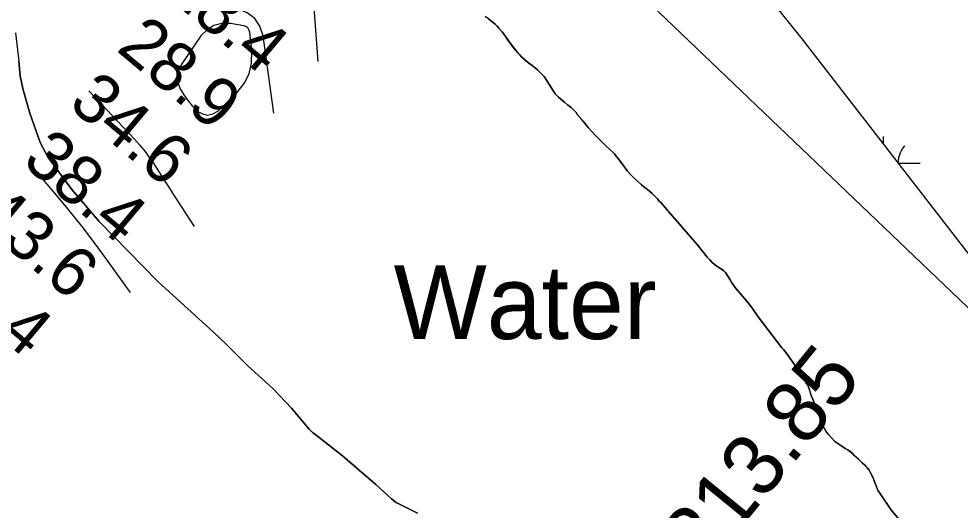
# Model space of a CAD drawing. Extents: x 3172231 to 3210228, y 940198 to 965780.
# Drawn here: x 3194853 to 3196129, y 948241 to 948908 of the extents above; entities that cross this region are included whole.
import ezdxf

# ---------------------------------------------------------------- set-up
doc = ezdxf.new("R2010")
doc.units = 0
for name, color, linetype in [('V-RIVR-IDEN', 7, 'Continuous'), ('V-RIVR-RANG', 7, 'Continuous'), ('V-RIVR-RANG-IDEN', 7, 'Continuous'), ('V-SITE-VEGE', 7, 'Continuous'), ('V-TOPO-BNDY', 7, 'Continuous'), ('V-TOPO-MAJR', 7, 'Continuous'), ('V-TOPO-MINR', 7, 'Continuous'), ('V-TOPO-SHOR', 7, 'Continuous'), ('V-WETL-SWMP', 7, 'Continuous')]:
    doc.layers.add(name, color=color, linetype=linetype)

msp = doc.modelspace()

# ---------------------------------------------------------------- linework, layer by layer
at = {"layer": 'V-SITE-VEGE'}
for p, q in [((3195489.691, 948907.734), (3195496.234, 948902.883)), ((3195496.234, 948902.883), (3195498.919, 948900.468)), ((3195498.919, 948900.468), (3195501.594, 948897.664)), ((3195501.594, 948897.664), (3195503.877, 948894.871)), ((3195503.877, 948894.871), (3195508.463, 948890.062)), ((3195508.463, 948890.062), (3195510.738, 948886.878)), ((3195510.738, 948886.878), (3195513.003, 948883.3)), ((3195513.003, 948883.3), (3195519.446, 948874.141)), ((3195519.446, 948874.141), (3195529.336, 948861.769)), ((3195529.336, 948861.769), (3195532.01, 948858.965)), ((3195532.01, 948858.965), (3195534.296, 948856.17)), ((3194854.602, 948830.054), (3194852.908, 948850.378)), ((3195534.296, 948856.17), (3195538.136, 948852.946)), ((3195538.136, 948852.946), (3195541.585, 948849.735)), ((3195541.585, 948849.735), (3195544.278, 948847.712)), ((3195544.278, 948847.712), (3195548.9, 948844.472)), ((3195548.9, 948844.472), (3195553.514, 948840.839)), ((3195553.514, 948840.839), (3195556.199, 948838.426)), ((3195556.199, 948838.426), (3195565.008, 948829.425)), ((3194858.761, 948811.525), (3194854.602, 948830.054)), ((3195565.008, 948829.425), (3195572.561, 948818.067)), ((3194867.627, 948779.88), (3194858.761, 948811.525)), ((3195572.561, 948818.067), (3195580.112, 948806.143)), ((3195580.112, 948806.143), (3195584.697, 948801.337)), ((3195584.697, 948801.337), (3195590.075, 948796.903)), ((3195590.075, 948796.903), (3195592.76, 948794.49)), ((3195592.76, 948794.49), (3195596.991, 948791.258)), ((3195596.991, 948791.258), (3195601.989, 948787.226)), ((3195601.989, 948787.226), (3195608.485, 948780.414)), ((3194881.783, 948740.151), (3194867.627, 948779.88)), ((3195608.485, 948780.414), (3195610.379, 948777.629)), ((3195610.379, 948777.629), (3195618.004, 948768.833)), ((3195618.004, 948768.833), (3195624.854, 948760.45)), ((3195624.854, 948760.45), (3195634.781, 948749.643)), ((3195634.781, 948749.643), (3195641.288, 948743.225)), ((3195641.288, 948743.225), (3195649.314, 948734.814)), ((3194892.871, 948719.464), (3194881.783, 948740.151)), ((3195649.314, 948734.814), (3195654.301, 948730.388)), ((3195654.301, 948730.388), (3195658.132, 948726.773)), ((3194924.828, 948675.964), (3194892.871, 948719.464)), ((3195658.132, 948726.773), (3195660.424, 948724.371)), ((3195660.424, 948724.371), (3195662.699, 948721.184)), ((3195662.699, 948721.184), (3195664.993, 948718.782)), ((3195664.993, 948718.782), (3195666.896, 948716.388)), ((3195666.896, 948716.388), (3195669.169, 948713.201)), ((3195669.169, 948713.201), (3195671.072, 948710.807)), ((3195671.072, 948710.807), (3195677.906, 948701.638)), ((3195677.906, 948701.638), (3195683.245, 948695.639)), ((3195683.245, 948695.639), (3195686.686, 948692.035)), ((3195686.686, 948692.035), (3195697.032, 948682.393)), ((3195697.032, 948682.393), (3195700.499, 948679.962)), ((3195700.499, 948679.962), (3195705.114, 948676.329)), ((3194961.972, 948632.68), (3194924.828, 948675.964)), ((3195705.114, 948676.329), (3195707.798, 948673.914)), ((3195707.798, 948673.914), (3195711.638, 948670.693)), ((3195711.638, 948670.693), (3195714.313, 948667.889)), ((3195714.313, 948667.889), (3195718.909, 948663.474)), ((3195718.909, 948663.474), (3195720.801, 948660.688)), ((3195720.801, 948660.688), (3195723.867, 948657.874)), ((3195723.867, 948657.874), (3195731.494, 948649.08)), ((3195731.494, 948649.08), (3195732.63, 948647.487)), ((3195732.63, 948647.487), (3195733.777, 948646.285)), ((3195733.777, 948646.285), (3195769.621, 948605.108)), ((3195041.537, 948551.491), (3194961.972, 948632.68)), ((3195769.621, 948605.108), (3195772.669, 948601.513)), ((3195772.669, 948601.513), (3195786.362, 948584.351)), ((3195786.362, 948584.351), (3195789.802, 948580.747)), ((3195789.802, 948580.747), (3195792.469, 948577.552)), ((3195792.469, 948577.552), (3195796.307, 948574.328)), ((3195796.307, 948574.328), (3195808.64, 948565.815)), ((3195808.64, 948565.815), (3195810.932, 948563.41)), ((3195117.08, 948482.6), (3195041.537, 948551.491)), ((3195810.932, 948563.41), (3195817.356, 948553.469)), ((3195817.356, 948553.469), (3195819.611, 948549.5)), ((3195819.611, 948549.5), (3195825.69, 948541.525)), ((3195825.69, 948541.525), (3195840.177, 948524.74)), ((3195840.177, 948524.74), (3195846.786, 948515.993)), ((3195846.786, 948515.993), (3195855.345, 948503.627)), ((3195855.345, 948503.627), (3195887.637, 948461.358)), ((3195134.696, 948465.737), (3195117.08, 948482.6)), ((3195163.389, 948436.871), (3195134.696, 948465.737)), ((3195887.637, 948461.358), (3195889.538, 948458.964)), ((3195889.538, 948458.964), (3195893.351, 948454.567)), ((3195893.351, 948454.567), (3195904.343, 948439.037)), ((3195182.57, 948419.972), (3195163.389, 948436.871)), ((3195904.343, 948439.037), (3195905.088, 948437.452)), ((3195905.088, 948437.452), (3195906.217, 948435.472)), ((3195906.217, 948435.472), (3195914.56, 948423.917)), ((3195914.56, 948423.917), (3195917.198, 948419.544)), ((3195197.859, 948405.86), (3195182.57, 948419.972)), ((3195917.198, 948419.544), (3195918.699, 948416.769)), ((3195918.699, 948416.769), (3195920.584, 948413.593)), ((3195920.584, 948413.593), (3195922.476, 948410.808)), ((3195922.476, 948410.808), (3195924.704, 948405.665)), ((3195222.738, 948379.477), (3195197.859, 948405.86)), ((3195924.704, 948405.665), (3195926.877, 948398.174)), ((3195926.877, 948398.174), (3195938.739, 948369.698)), ((3195246.74, 948351.106), (3195222.738, 948379.477)), ((3195938.739, 948369.698), (3195942.743, 948356.683)), ((3195250.937, 948346.312), (3195246.74, 948351.106)), ((3195942.743, 948356.683), (3195948, 948347.162)), ((3195948, 948347.162), (3195950.284, 948344.366)), ((3195253.638, 948344.682), (3195250.937, 948346.312)), ((3195291.704, 948314.81), (3195253.638, 948344.682)), ((3195950.284, 948344.366), (3195959.449, 948334.36)), ((3195959.449, 948334.36), (3195967.546, 948329.078)), ((3195967.546, 948329.078), (3195970.241, 948327.059)), ((3195970.241, 948327.059), (3195973.326, 948325.027)), ((3195973.326, 948325.027), (3195976.801, 948322.985)), ((3195976.801, 948322.985), (3195983.345, 948318.136)), ((3195337.004, 948276.152), (3195291.704, 948314.81)), ((3195983.345, 948318.136), (3195985.628, 948315.34)), ((3195985.628, 948315.34), (3195994.066, 948307.701)), ((3195994.066, 948307.701), (3195996.358, 948305.299)), ((3195996.358, 948305.299), (3196000.198, 948302.075)), ((3196000.198, 948302.075), (3196005.914, 948295.282)), ((3196005.914, 948295.282), (3196007.415, 948292.507)), ((3196007.415, 948292.507), (3196010.78, 948285.769)), ((3196010.78, 948285.769), (3196013.745, 948278.652)), ((3195358.08, 948256.466), (3195337.004, 948276.152)), ((3196013.745, 948278.652), (3196015.209, 948274.311)), ((3196015.209, 948274.311), (3196016.684, 948270.36)), ((3196016.684, 948270.36), (3196018.183, 948267.583)), ((3196018.183, 948267.583), (3196021.206, 948262.813)), ((3196021.206, 948262.813), (3196035.421, 948241.825)), ((3195364.623, 948251.615), (3195358.08, 948256.466)), ((3195382.517, 948242.53), (3195364.623, 948251.615)), ((3195393.656, 948237.225), (3195382.517, 948242.53)), ((3196035.421, 948241.825), (3196048.367, 948226.26))]:
    msp.add_line(p, q, dxfattribs=at)
at = {"layer": 'V-TOPO-BNDY'}
msp.add_line((3194332.024, 950245.511), (3197716.878, 947007.215), dxfattribs=at)
at = {"layer": 'V-TOPO-MAJR'}
for points in [[(3195258.938, 948850.046), (3195250.642, 948959.823), (3195245.961, 948974.907), (3195238.352, 948987.151), (3195226.35, 948995.138), (3195211.419, 949000.286), (3195157.516, 949006.052)], [(3194873.08, 948704.352), (3194903.66, 948668.48), (3194921.251, 948647.311), (3194938.477, 948625.856), (3194955.155, 948603.973), (3194971.469, 948581.805), (3194999.012, 948543.371), (3195003.741, 948536.65)]]:
    msp.add_lwpolyline(points, dxfattribs=at)
at = {"layer": 'V-TOPO-MINR'}
for points in [[(3195198.48, 948779.828), (3195184.19, 948884.587), (3195179.701, 948897.56), (3195172.88, 948908.347), (3195162.558, 948915.854), (3195149.904, 948921.175), (3195081.635, 948935.05)], [(3195108.812, 948776.917), (3195115.819, 948778.61), (3195122.827, 948782.564), (3195148.636, 948807.413), (3195158.326, 948819.867), (3195165.374, 948833.269), (3195168.461, 948848.093), (3195168.906, 948863.866), (3195165.915, 948889.775), (3195164.884, 948892.865), (3195163.281, 948895.413), (3195160.821, 948897.147), (3195157.789, 948898.338), (3195139.736, 948901.384), (3195128.042, 948901.23), (3195117.336, 948898.748), (3195108.113, 948892.772), (3195099.879, 948884.466), (3195073.125, 948845.429), (3195069.499, 948837.443), (3195067.72, 948829.368), (3195068.71, 948821.159), (3195071.547, 948812.86), (3195076.516, 948804.738), (3195081.936, 948796.962), (3195088.032, 948789.704), (3195094.58, 948782.792), (3195094.802, 948782.577), (3195101.806, 948778.617), (3195108.812, 948776.917)], [(3194947.966, 948810.136), (3194980.145, 948775.877), (3194987.54, 948768), (3194994.933, 948760.121), (3195002.323, 948752.239), (3195009.711, 948744.355), (3195016.866, 948736.289), (3195023.715, 948727.985), (3195030.106, 948719.322), (3195036.19, 948710.421), (3195036.82, 948709.444), (3195042.985, 948699.872), (3195049.146, 948690.297)], [(3195049.146, 948690.297), (3195055.301, 948680.718), (3195061.452, 948671.137), (3195090.459, 948625.92)]]:
    msp.add_lwpolyline(points, dxfattribs=at)
at = {"layer": 'V-TOPO-SHOR'}
for points in [[(3195572.561, 948818.069), (3195565.008, 948829.425), (3195556.199, 948838.426), (3195553.514, 948840.839), (3195548.9, 948844.472), (3195544.278, 948847.712), (3195541.585, 948849.735), (3195538.136, 948852.946), (3195534.296, 948856.17), (3195532.01, 948858.965), (3195529.336, 948861.769), (3195525.15, 948866.959), (3195521.347, 948871.747), (3195519.446, 948874.141), (3195516.034, 948878.921), (3195513.003, 948883.3), (3195510.738, 948886.878), (3195508.463, 948890.062), (3195503.877, 948894.871), (3195501.594, 948897.664), (3195498.919, 948900.468), (3195496.234, 948902.883), (3195489.691, 948907.734), (3195485.066, 948910.976)], [(3194848.277, 948888.899), (3194852.908, 948850.378), (3194854.602, 948830.054), (3194858.761, 948811.525), (3194867.627, 948779.88), (3194881.783, 948740.151), (3194892.871, 948719.464), (3194924.828, 948675.964), (3194961.972, 948632.68), (3195041.537, 948551.491)], [(3196048.367, 948226.26), (3196035.421, 948241.825), (3196024.235, 948258.434), (3196021.206, 948262.813), (3196018.183, 948267.583), (3196016.684, 948270.36), (3196015.209, 948274.311), (3196013.745, 948278.652), (3196010.78, 948285.771), (3196007.415, 948292.507), (3196005.914, 948295.284), (3196002.481, 948299.28), (3196000.198, 948302.075), (3195996.358, 948305.299), (3195994.066, 948307.701), (3195991.381, 948310.114), (3195985.628, 948315.34), (3195983.345, 948318.136), (3195979.496, 948320.966), (3195976.801, 948322.987), (3195973.326, 948325.027), (3195970.241, 948327.059), (3195967.546, 948329.078), (3195959.449, 948334.36), (3195950.284, 948344.366), (3195948, 948347.162), (3195942.743, 948356.683), (3195938.739, 948369.698), (3195926.877, 948398.174), (3195925.788, 948401.723), (3195924.704, 948405.665), (3195922.476, 948410.808), (3195920.584, 948413.593), (3195918.699, 948416.769), (3195917.198, 948419.546), (3195914.56, 948423.917), (3195906.217, 948435.47), (3195905.088, 948437.452), (3195904.343, 948439.037), (3195893.351, 948454.567), (3195889.538, 948458.964), (3195887.637, 948461.358), (3195855.345, 948503.627), (3195846.786, 948515.993), (3195840.177, 948524.74), (3195825.69, 948541.525), (3195819.611, 948549.5), (3195817.356, 948553.469), (3195810.932, 948563.41), (3195808.64, 948565.815), (3195796.309, 948574.328), (3195792.469, 948577.552), (3195789.802, 948580.747), (3195786.362, 948584.351), (3195774.569, 948599.117), (3195772.669, 948601.511), (3195769.619, 948605.108), (3195733.777, 948646.285), (3195732.63, 948647.487), (3195731.494, 948649.08), (3195723.867, 948657.874), (3195720.801, 948660.688), (3195718.909, 948663.474), (3195714.313, 948667.889), (3195711.638, 948670.693), (3195707.798, 948673.916), (3195705.114, 948676.329), (3195700.499, 948679.962), (3195697.032, 948682.393), (3195686.686, 948692.035), (3195683.245, 948695.639), (3195677.906, 948701.638), (3195673.728, 948707.219), (3195671.072, 948710.807), (3195669.169, 948713.201), (3195666.896, 948716.388), (3195664.993, 948718.782), (3195662.699, 948721.184), (3195660.424, 948724.371), (3195658.132, 948726.773), (3195654.301, 948730.388), (3195649.314, 948734.814), (3195646.256, 948738.019), (3195643.581, 948740.822), (3195641.288, 948743.225), (3195634.781, 948749.643), (3195624.854, 948760.45), (3195618.004, 948768.835), (3195614.954, 948772.431), (3195610.377, 948777.629), (3195608.485, 948780.414), (3195601.989, 948787.226), (3195596.991, 948791.258), (3195592.76, 948794.49), (3195590.075, 948796.903), (3195584.697, 948801.337), (3195580.112, 948806.143), (3195577.847, 948809.721), (3195572.561, 948818.069)], [(3195041.537, 948551.491), (3195117.08, 948482.6), (3195134.696, 948465.739), (3195163.389, 948436.871), (3195182.57, 948419.972), (3195197.859, 948405.86), (3195222.738, 948379.477), (3195246.74, 948351.108), (3195250.937, 948346.312), (3195253.638, 948344.682), (3195291.704, 948314.81), (3195337.004, 948276.152), (3195358.08, 948256.466), (3195364.623, 948251.615), (3195382.517, 948242.53), (3195393.656, 948237.225)]]:
    msp.add_lwpolyline(points, dxfattribs=at)
at = {"layer": 'V-WETL-SWMP'}
for p, q in [((3195915.087, 948880.76), (3195619.376, 949250.55)), ((3196543.471, 948067.222), (3195915.087, 948880.76)), ((3196025.32, 948738.047), (3196025.388, 948748.11)), ((3196045.46, 948711.973), (3196075.142, 948711.771))]:
    msp.add_line(p, q, dxfattribs=at)
msp.add_arc((3196080.388, 948712.21), 35.246, 138.838162, 179.717879, dxfattribs=at)

# ---------------------------------------------------------------- texts
at = {"layer": 'V-RIVR-IDEN'}
msp.add_text('Water', height=99.9998, dxfattribs=at).set_placement((3195361.155, 948473.312))
at = {"layer": 'V-RIVR-RANG'}
for s, p in [('28.4', (3195047.848, 948942.02)), ('28.9', (3194983.588, 948865.4)), ('34.6', (3194918.318, 948789.626)), ('38.4', (3194855.678, 948711.65)), ('43.6', (3194790.205, 948636.046)), ('42.4', (3194727.564, 948558.069))]:
    msp.add_text(s, height=67, rotation=320.028326, dxfattribs=at).set_placement(p)
at = {"layer": 'V-RIVR-RANG-IDEN'}
msp.add_text('R-313.85', height=82.9998, rotation=50.802318, dxfattribs=at).set_placement((3195709.254, 948066.353))

doc.saveas('drawing.dxf')
